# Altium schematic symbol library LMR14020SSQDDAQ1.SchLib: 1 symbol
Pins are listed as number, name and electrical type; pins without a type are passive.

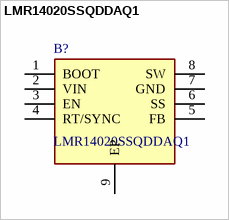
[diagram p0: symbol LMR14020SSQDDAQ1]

## LMR14020SSQDDAQ1
designator B?
Automotive 40V, 2A SIMPLE SWITCHER, 2.2MHz Step-Down Regulator with 40uA IQ; Manufacturer_Name: Texas Instruments; Geometry.Height: 1.7mm
footprint SOIC127P600X170-9N
pins: 1 BOOT, 2 VIN, 3 EN, 4 RT/SYNC, 5 FB, 6 SS, 7 GND, 8 SW, 9 EP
